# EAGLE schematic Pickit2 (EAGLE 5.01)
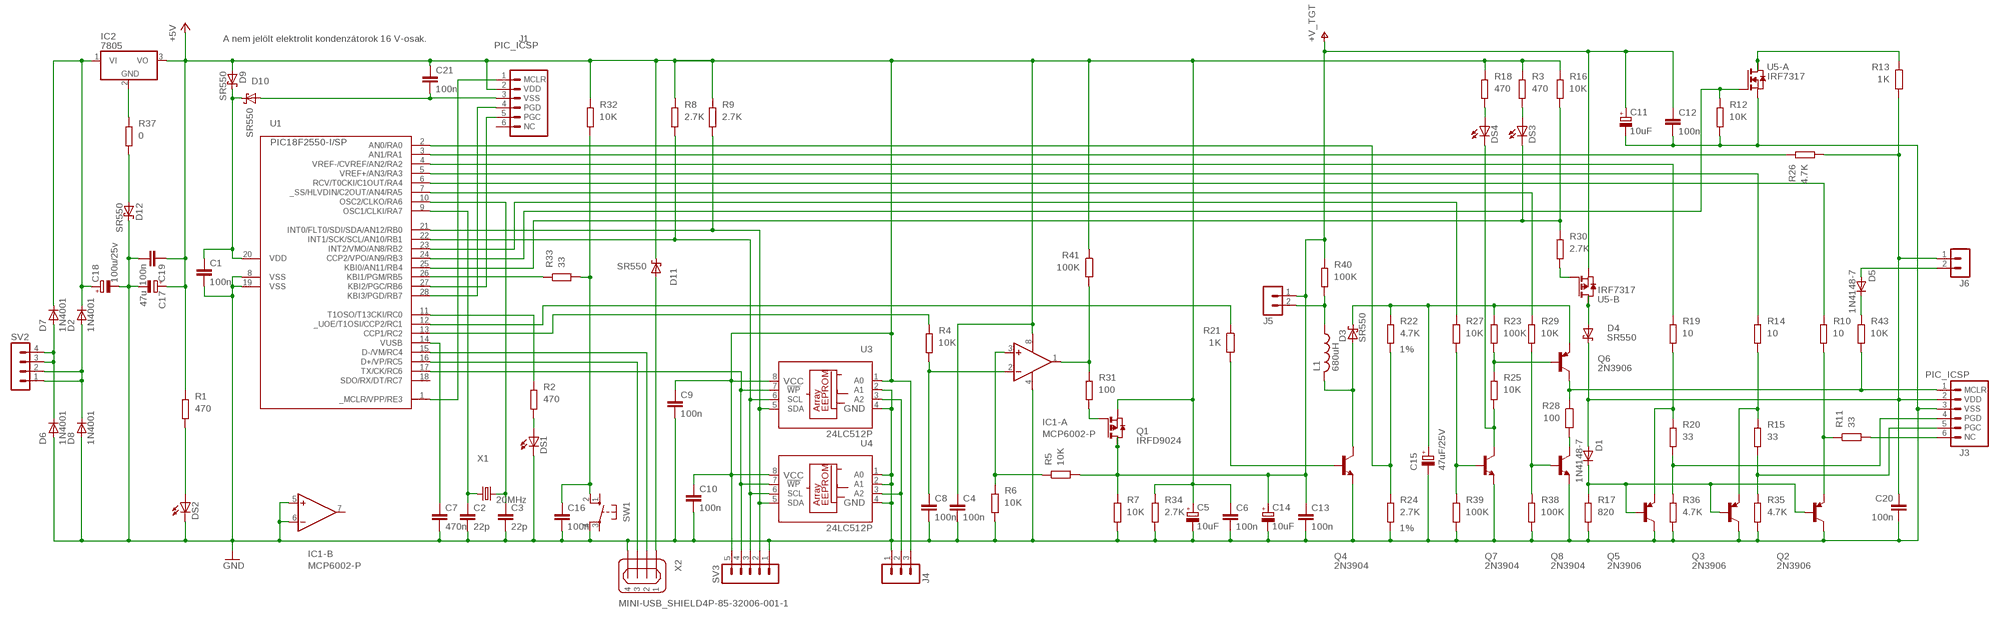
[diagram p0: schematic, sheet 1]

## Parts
C1  100n  C-EU_C050  [C050-025X075]
C2  22p  C-EU_025  [C025-025X050]
C3  22p  C-EU_025  [C025-025X050]
C4  100n  C-EU_C050  [C050-025X075]
C5  10uF  CPOL-EUE2.5-6  [E2,5-6]
C6  100n  C-EU_C050  [C050-025X075]
C7  470n  C-EU_C050  [C050-025X075]
C8  100n  C-EU_C050  [C050-025X075]
C9  100n  C-EU_C050  [C050-025X075]
C10  100n  C-EU_C050  [C050-025X075]
C11  10uF  CPOL-EUE2.5-6  [E2,5-6]
C12  100n  C-EU_C050  [C050-025X075]
C13  100n  C-EU_C050  [C050-025X075]
C14  10uF  CPOL-EUE2.5-6  [E2,5-6]
C15  47uF/25V  CPOL-EUE2.5-6  [E2,5-6]
C16  100n  C-EU_C050  [C050-025X075]
C17  47u  CPOL-EUE5-10.5  [E5-10,5]
C18  100u/25v  CPOL-EUE5-10.5  [E5-10,5]
C19  100n  C-EU_C050  [C050-025X075]
C20  100n  C-EU_C050  [C050-025X075]
C21  100n  C-EU_C050  [C050-025X075]
D1  1N4148-7  [D-7,5/R]
D2  1N4001  1N4007/7MM  [DO34-7]
D3  SR550  [DO35-10/R]
D4  SR550  [DO35-10/R]
D5  1N4148-7  [D-7,5/R]
D6  1N4001  1N4007/7MM  [DO34-7]
D7  1N4001  1N4007/7MM  [DO34-7]
D8  1N4001  1N4007/7MM  [DO34-7]
D9  SR550  [DO35-10/R]
D10  SR550  [DO35-10/R]
D11  SR550  [DO35-10/R]
D12  SR550  [DO35-10/R]
DS1  LEDLED_03  [LED3MM]
DS2  LEDLED_03  [LED3MM]
DS3  LEDLED_03  [LED3MM]
DS4  LEDLED_03  [LED3MM]
IC1  MCP6002-P  [DIL08]
IC2  7805  [TO220]
J1  PIC_ICSP  [MA06-1]
J3  PIC_ICSP  [MA06-1]
J4  MA03-1  [MA03-1]
J5  MA2-1  [MA2-1]
J6  MA2-1  [MA2-1]
L1  680uH  L-US0207/12  [0207/12]
Q1  IRFD9024  [DIL04]
Q2  2N3906  [TO92-]
Q3  2N3906  [TO92-]
Q4  2N3904  [TO92-]
Q5  2N3906  [TO92-]
Q6  2N3906  [TO92-]
Q7  2N3904  [TO92-]
Q8  2N3904  [TO92-]
R1  470  R-EU_204  [0204/7]
R2  470  R-EU_204  [0204/7]
R3  470  R-EU_204  [0204/7]
R4  10K  R-EU_204  [0204/7]
R5  10K  R-EU_204  [0204/7]
R6  10K  R-EU_204  [0204/7]
R7  10K  R-EU_204  [0204/7]
R8  2.7K  R-EU_204  [0204/7]
R9  2.7K  R-EU_204  [0204/7]
R10  10  R-EU_204  [0204/7]
R11  33  R-EU_204  [0204/7]
R12  10K  R-EU_204  [0204/7]
R13  1K  R-EU_204  [0204/7]
R14  10  R-EU_204  [0204/7]
R15  33  R-EU_204  [0204/7]
R16  10K  R-EU_204  [0204/7]
R17  820  R-EU_204  [0204/7]
R18  470  R-EU_204  [0204/7]
R19  10  R-EU_204  [0204/7]
R20  33  R-EU_204  [0204/7]
R21  1K  R-EU_204  [0204/7]
R22  4.7K  R-EU_204  [0204/7]
R23  100K  R-EU_204  [0204/7]
R24  2.7K  R-EU_204  [0204/7]
R25  10K  R-EU_204  [0204/7]
R26  4.7K  R-EU_204  [0204/7]
R27  10K  R-EU_204  [0204/7]
R28  100  R-EU_204  [0204/7]
R29  10K  R-EU_204  [0204/7]
R30  2.7K  R-EU_204  [0204/7]
R31  100  R-EU_204  [0204/7]
R32  10K  R-EU_204  [0204/7]
R33  33  R-EU_204  [0204/7]
R34  2.7K  R-EU_204  [0204/7]
R35  4.7K  R-EU_204  [0204/7]
R36  4.7K  R-EU_204  [0204/7]
R37  0  R-EU_204  [0204/7]
R38  100K  R-EU_204  [0204/7]
R39  100K  R-EU_204  [0204/7]
R40  100K  R-EU_204  [0204/7]
R41  100K  R-EU_204  [0204/7]
R43  10K  R-EU_204  [0204/7]
SV2  MA04-1  [MA04-1]
SV3  MA05-1  [MA05-1]
SW1  10-XX  [B3F-10XX]
U1  PIC18F2550-I/SP  [DIL28-3]
U3  24LC512P  [DIL8]
U4  24LC512P  [DIL8]
U5  IRF7317  [SO8]
X1  20MHz  CRYTALHC49S  [HC49/S]
X2  MINI-USB_SHIELD4P-85-32006-001-1  [85-32006-001-1]

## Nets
+5V: C4.P$1 C5.+ C6.P$1 C9.P$1 C10.P$1 C17.+ C19.P$1 C21.P$1 D9.A D11.C IC1.8(-A:V+) IC2.3(VO) J1.2(VDD) J4.3 Q1.4(S) R1.P$1 R3.P$1 R8.P$1 R9.P$1 R16.P$1 R18.P$1 R32.P$1 R34.P$1 R41.P$1 SV3.5 U3.1(A0) U3.8(VCC) U4.8(VCC)
+V_TGT: C11.+ C12.P$1 C13.P$1 C14.+ J5.1 Q1.1(D) Q1.2(D2) R5.P$2 R7.P$1 R40.P$1 U5.3(-B:S)
AUX: R10.P$1 U1.6(RCV/T0CKI/C1OUT/RA4)
D+: U1.16(D+/VP/RC5) X2.3
D-: U1.15(D-/VM/RC4) X2.2
GND: C1.P$2 C2.P$2 C3.P$2 C4.P$2 C5.- C6.P$2 C7.P$2 C8.P$2 C9.P$2 C10.P$2 C11.- C12.P$2 C13.P$2 C14.- C15.- C16.P$2 C17.- C18.- C19.P$2 C20.P$2 D6.A D8.A D12.C DS1.K(C) DS2.K(C) IC1.4(-A:V-) IC1.5(-B:+IN) IC1.6(-B:-IN) J3.3(VSS) J4.1 Q2.1(C) Q3.1(C) Q4.3(E) Q5.1(C) Q7.3(E) Q8.3(E) R6.P$2 R7.P$2 R12.P$2 R17.P$2 R24.P$2 R34.P$2 R35.P$2 R36.P$2 R38.P$2 R39.P$2 SV3.1 SW1.4(P1) U1.8(VSS) U1.19(VSS) U3.2(A1) U3.4(GND) U4.1(A0) U4.2(A1) U4.4(GND) U5.1(-A:S) X2.4
ICSPCLK: R14.P$1 U1.5(VREF+/AN3/RA3)
ICSPDAT: R19.P$1 U1.4(VREF-/CVREF/AN2/RA2)
MCLR: J1.1(MCLR) U1.1(_MCLR/VPP/RE3)
MCLR_TGT: R29.P$1 U1.7(_SS/HLVDIN/C2OUT/AN4/RA5)
N$1: C16.P$1 R32.P$2 R33.P$2 SW1.2(S1)
N$2: DS2.A R1.P$2
N$3: C7.P$1 U1.14(VUSB)
N$4: R2.P$1 U1.11(T1OSO/T13CKI/RC0)
N$5: C8.P$1 IC1.2(-A:-IN) R4.P$2
N$6: DS1.A R2.P$2
N$7: IC1.3(-A:+IN) R5.P$1 R6.P$1
N$8: C2.P$1 U1.9(OSC1/CLKI/RA7) X1.1
N$9: C3.P$1 U1.10(OSC2/CLKO/RA6) X1.2
N$10: IC1.1(-A:OUT) R31.P$1 R41.P$2
N$11: Q1.3(G) R31.P$2
N$12: D3.A L1.2 Q4.1(C)
N$13: C15.+ D3.C Q6.3(E) R22.P$1 R23.P$1
N$14: J5.2 L1.1 R40.P$2
N$15: DS4.K(C) Q7.1(C) R25.P$2
N$16: J3.1(MCLR) Q6.1(C) R28.P$1 R43.P$2
N$17: Q8.1(C) R28.P$2
N$18: Q6.2(B) R23.P$2 R25.P$1
N$19: Q7.2(B) R27.P$2 R39.P$1
N$20: Q8.2(B) R29.P$2 R38.P$1
N$21: DS4.A R18.P$2
N$22: J3.4(PGD) R20.P$2 R36.P$1
N$23: J3.5(PGC) R15.P$2 R35.P$1
N$24: J3.6(NC) R11.P$2
N$25: Q5.3(E) R19.P$2 R20.P$1
N$26: Q3.3(E) R14.P$2 R15.P$1
N$27: Q2.3(E) R10.P$2 R11.P$1
N$28: D1.C Q2.2(B) Q3.2(B) Q5.2(B) R17.P$1
N$30: D5.C R43.P$1
N$31: D4.A U5.5(-B:D) U5.6(-B:D2)
N$32: R13.P$1 U5.7(-A:D) U5.8(-A:D2)
N$33: DS3.A R3.P$2
N$34: R30.P$2 U5.4(-B:G)
N$35: D5.A J6.2
N$36: C21.P$2 D10.A J1.3(VSS)
N$37: C1.P$1 D9.C D10.C U1.20(VDD)
N$38: J4.2 U3.3(A2) U4.3(A2)
N$39: D11.A X2.1
N$40: D12.A R37.P$2
N$41: IC2.2(GND) R37.P$1
N$51: D6.C D7.A SV2.3 SV2.4
N$58: D2.A D8.C SV2.1 SV2.2
N$60: C18.+ D2.C D7.C IC2.1(VI)
PGC: J1.5(PGC) U1.27(KBI2/PGC/RB6)
PGD: J1.4(PGD) U1.28(KBI3/PGD/RB7)
PGM: R33.P$1 U1.26(KBI1/PGM/RB5)
Q4: Q4.2(B) R21.P$2
SCL: R8.P$2 SV3.3 U1.22(INT1/SCK/SCL/AN10/RB1) U3.6(SCL) U4.6(SCL)
SDA: R9.P$2 SV3.2 U1.21(INT0/FLT0/SDI/SDA/AN12/RB0) U3.5(SDA) U4.5(SDA)
VDD_TGT: C20.P$1 D1.A D4.C J3.2(VDD) J6.1 R13.P$2 R26.P$2
VDD_TGT_ADJ: R4.P$1 U1.13(CCP1/RC2)
VDD_TGT_FB: R26.P$1 U1.3(AN1/RA1)
VDD_TGT_N: R12.P$1 U1.24(CCP2/VPO/AN9/RB3) U5.2(-A:G)
VDD_TGT_P: DS3.K(C) R16.P$2 R30.P$1 U1.25(KBI0/AN11/RB4)
VPP_FEEDBACK: R22.P$2 R24.P$1 U1.2(AN0/RA0)
VPP_ON: R27.P$1 U1.23(INT2/VMO/AN8/RB2)
VPP_PUMP: R21.P$1 U1.12(_UOE/T1OSI/CCP2/RC1)
WP: SV3.4 U1.17(TX/CK/RC6) U3.7(!WP) U4.7(!WP)
Unconnected: IC1.7(-B:OUT) J1.6(NC) SW1.1(S) SW1.3(P) U1.18(SDO/RX/DT/RC7) X2.M1(S1) X2.M2(S2)

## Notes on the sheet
- A nem jelölt elektrolit kondenzátorok 16 V-osak.
- 1%
- 1%

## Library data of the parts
C1-C4 C6-C10 C12 C13 C16 C19-C21 = 2gab:C-EU_
C5 C11 C14 C15 = 2gab:CPOL-EU: POLARIZED CAPACITOR, European symbol
C17 C18 = rcl:CPOL-EU: POLARIZED CAPACITOR, European symbol
D1 D5 = 2gab:1N4148: DIODE
D2 D6-D8 = 2gab:1N4007: DIODE
D3 D4 D9-D12 = 2gab:SR550: SCHOTTKY BARRIER RECTIFIER
DS1-DS4 = 2gab:LED
IC1 = 2gab:MCP6002: 1 MHz Bandwidth Low Power Op Amp Available in SC-70-5 and SOT-23-5 packages 1 MHz Gain Bandwidth Product (typ.) Rail-to-Rail Input/Output Supply Voltage: 1.8V to 5.5V Supply Current: IQ = 100 ?A (typ.) 90° Phase Margin (typ.) Temperature Range: - Industrial: -40°C to +85°C - Extended: -40°C to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
IC2 = 2gab:78*: Positive VOLTAGE REGULATOR
J1 J3 = 2gab:PIC_ICSP: PIC ICSP Signals ICSP provides 6 connections from the pic ICSP programmer to your board as follows : 1 VPP (or MCLRn) Programming voltage (usually 13V). 2 Vcc Power (usually 5V). 3 GND Ground (zero volts). 4 PGD - Data usual port and connection RB7. 5 PGC - Clock usual port and connection RB6. 6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
J4 = 2gab:MA03-1: PIN HEADER
J5 J6 = 2gab:MA2-1: PIN HEADER
L1 = rcl:L-US: INDUCTOR, American symbol
Q1 = 2gab:IRFD9024: Power MOSFET Third generation Power MOSFETs from Vishay provide the designer with the best combination of fast switching, ruggedized device design, low on-resistance and cost-effectiveness. The 4 pin DIP package is a low cost machine-insertable case style which can be stacked in multiple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
Q2 Q3 Q5 Q6 = 2gab:2N3906: 2N3906 PNP General Purpose Amplifier This device is designed for general purpose amplifier and switching applications at collector currents of 10 ?A to 100 mA.
Q4 Q7 Q8 = 2gab:2N3904: 2N3904 PNP General Purpose Amplifier This device is designed for general purpose amplifier and switching applications at collector currents of 10 ?A to 100 mA.
R1-R41 R43 = 2gab:R-EU_
SV2 = con-lstb:MA04-1: PIN HEADER
SV3 = 2gab:MA05-1: PIN HEADER
SW1 = switch-omron:10-XX: OMRON SWITCH
U1 = microchip-pic18fxx5x:PIC18*2550: PIC18*2550 Microchip FLASH Microcontroller with FS-USB DEVICE FEATURES FeaturePIC18*2550 Program Memory (bytes) 32k Program Memory (instructions) 16384 I/O Ports Ports A, B, C, (E) Capture/Compare/PWM Modules 2 Enhanced Capture/Compare/PWM Modules 0 Parallel Communications (PSP) No 10-bit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
U3 U4 = 2gab:24LC512: 512K I2C? CMOS Serial EEPROM Features: ? Low-power CMOS technology: - Maximum write current 5 mA at 5.5V - Maximum read current 400 ?A at 5.5V - Standby current 100 nA typical at 5.5V ? 2-wire serial interface bus, I2C? compatible ? Cascadable for up to eight devices ? Self-timed erase/write cycle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
U5 = 2gab:IRF7317: IRF7317 HEXFET Power MOSFET Fifth Generation HEXFETs from International Rectifier utilize advanced processing techniques to achieve extremely low on-resistance per silicon area. This benefit, combined with the fast switching speed and ruggedized device design that HEXFET Power MOSFETs are well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
X1 = crystal:CRYTAL: CRYSTAL
X2 = con-cypressindustries:MINI-USB_SHIELD4P-: MINI USB 4 Pol. Source: www.cypressindustries.com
